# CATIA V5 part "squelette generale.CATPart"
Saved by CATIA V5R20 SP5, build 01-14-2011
Part number: squelette generale
Publications: "Plan.1", "Point.1", "rayon de liaison", "Longueur de barre AB et BC", "Largeur", "epaisseur"
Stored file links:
  F:\projet\yyang_IAO\squelette generale.CATPart
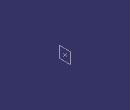
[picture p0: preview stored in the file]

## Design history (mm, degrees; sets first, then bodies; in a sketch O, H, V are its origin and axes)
Parameters
  `rayon de liaison` = 5 mm
  `Longueur de barre AB et BC` = 200 mm
  Largeur = 20 mm
  epaisseur = 10 mm
Body1 (main body)
  Plane1: type Offset, RefPlane yz-plane, Offset 0
  Point1: (0, 0, 0)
